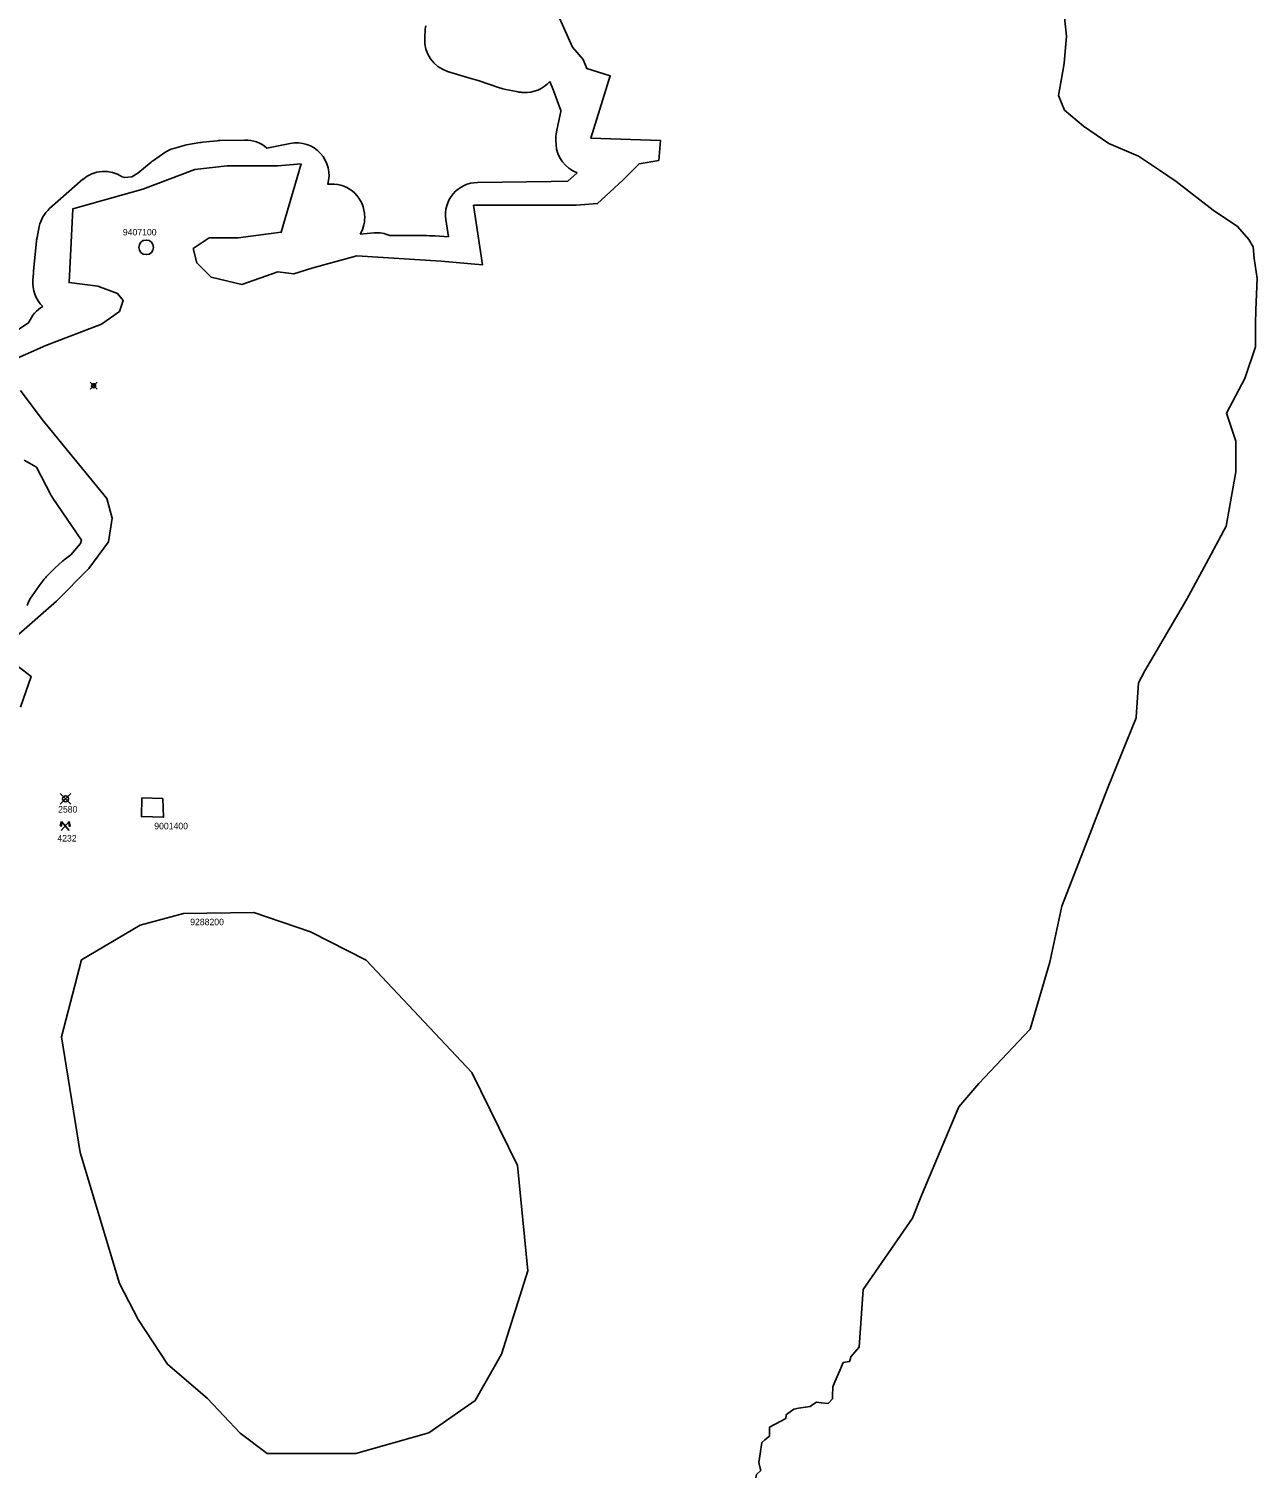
# Model space of a CAD drawing. Extents: x -546762 to -536351, y -1046851 to -1035695.
# Drawn here: x -542331 to -540434, y -1043037 to -1040804 of the extents above; entities that cross this region are included whole.
import ezdxf

# ---------------------------------------------------------------- set-up
doc = ezdxf.new("R2010")
doc.units = 0
for name, color, linetype in [('Vrstva 23', 7, 'Continuous'), ('Vrstva 24', 7, 'Continuous'), ('Vrstva 43', 7, 'Continuous'), ('Vrstva 49', 7, 'Continuous'), ('Vrstva 50', 7, 'Continuous'), ('Vrstva 53', 7, 'Continuous')]:
    doc.layers.add(name, color=color, linetype=linetype)

msp = doc.modelspace()

# ---------------------------------------------------------------- linework, layer by layer
at = {"layer": 'Vrstva 23'}
for points in [[(-541718.7, -1040804.2), (-541719.6, -1040818.5)], [(-541684.4, -1040869.7), (-541653.4, -1040879.2)], [(-541652.1, -1040879.6), (-541637.2, -1040883.7), (-541603.9, -1040895.3)], [(-541597, -1040897.2), (-541575.4, -1040901.4)], [(-541569.2, -1040902.2), (-541567.4, -1040902.3)], [(-541526.5, -1040885.3), (-541520.9, -1040899.1), (-541509.4, -1040930.2), (-541509.6, -1040931.9), (-541513.6, -1040950.9), (-541516.2, -1040963.1)], [(-542091.3, -1040984.3), (-542105.7, -1040988.2)], [(-542066.8, -1040979.7), (-542087.3, -1040983.4)], [(-542040.1, -1040976.8), (-542062.9, -1040979.1)], [(-541997.7, -1040975.7), (-542036.2, -1040976.6)], [(-541927.3, -1040981), (-541963.3, -1040988.3)], [(-541517.1, -1040976.5), (-541516.8, -1040982.4)], [(-542142.3, -1041009.9), (-542162.5, -1041026.7), (-542172.2, -1041032.5), (-542182.9, -1041033.6), (-542186.9, -1041032.4)], [(-542120.9, -1040995.1), (-542138.6, -1041007.2)], [(-542247.6, -1041036.4), (-542298.9, -1041081.5)], [(-541484.2, -1041026.3), (-541498.6, -1041039.1), (-541524.2, -1041039.6), (-541638.2, -1041041.2)], [(-541812.5, -1041090.9), (-541812.7, -1041088.9)], [(-541686.9, -1041098.6), (-541683, -1041125.1), (-541703.5, -1041123.9), (-541712.2, -1041123.4), (-541712.2, -1041123.4), (-541717.1, -1041123.1)], [(-542315, -1041109.4), (-542318.4, -1041126.4)], [(-541797.8, -1041119.1), (-541819.2, -1041121)], [(-541720.1, -1041123), (-541773.6, -1041123)], [(-542319.1, -1041131.5), (-542323.6, -1041178.4), (-542323.9, -1041181.9)], [(-542323.9, -1041181.9), (-542324.8, -1041191.7)], [(-542330.9, -1041257.1), (-542331.1, -1041257.4), (-542348.4, -1041269.3)], [(-542338.1, -1041469.8), (-542319, -1041480.8), (-542297.2, -1041523.3)], [(-542294.1, -1041528.6), (-542249.8, -1041593.7), (-542251.2, -1041598.6), (-542266.4, -1041615.9), (-542276.4, -1041623.8)], [(-542292.3, -1041638.1), (-542304, -1041650)], [(-542278.9, -1041625.9), (-542290.1, -1041636)], [(-542308.9, -1041655.7), (-542314.9, -1041664), (-542326, -1041679.3)]]:
    msp.add_lwpolyline(points, dxfattribs=at)
for centre, start, end in [((-541668.8, -1040807.6), 170.549, 176.1275), ((-541669.7, -1040821.9), 176.1275, 252.9674), ((-541638.7, -1040831.4), 252.9674, 254.5029), ((-541587.5, -1040848.1), 250.7987, 259.0889), ((-541565.9, -1040852.3), 259.0889, 266.2483), ((-541564.1, -1040852.4), 266.2483, 318.7681), ((-541467.2, -1040973.5), 168.1042, 183.4741), ((-542092.8, -1041036.5), 104.9586, 124.2627), ((-542078.4, -1041032.6), 100.3269, 104.9586), ((-542057.8, -1041028.9), 95.8202, 100.3269), ((-542035, -1041026.6), 91.3381, 95.8202), ((-541996.5, -1041025.7), 48.3603, 91.3381), ((-541917.4, -1041030.1), 343.6813, 101.3798), ((-541466.9, -1040979.4), 183.4741, 249.7552), ((-542110.4, -1041048.5), 124.2627, 129.5469), ((-542214.6, -1041074), 56.332, 131.2869), ((-541862.5, -1041093.6), 5.4, 97.9371), ((-541637.5, -1041091.2), 90.8025, 188.4933), ((-542265.9, -1041119.1), 131.2869, 168.7675), ((-541862.3, -1041095.6), 329.5491, 5.4), ((-542269.3, -1041136.2), 168.7675, 174.5913), ((-541793.5, -1041168.9), 66.5513, 95.0005), ((-541720.1, -1041173), 86.5922, 90.0098), ((-542275, -1041196.4), 174.5845, 226.4359), ((-542274.1, -1041186.6), 174.5362, 174.5845), ((-542284.6, -1041276), 119.8655, 157.8197), ((-542252.7, -1041500.5), 207.2129, 214.1842), ((-542256.7, -1041673.1), 132.0575, 135.4591), ((-542245.4, -1041663), 128.3522, 132.0575), ((-542268.4, -1041685.1), 135.4591, 143.9971), ((-542285.6, -1041708.7), 143.9771, 163.5215)]:
    msp.add_arc(centre, 50, start, end, dxfattribs=at)
at = {"layer": 'Vrstva 24'}
for points in [[(-541524.7, -1040757.2), (-541491.4, -1040832.2), (-541474.7, -1040851.6), (-541469.1, -1040865.5), (-541433, -1040876.6), (-541462.9, -1040973), (-541355.3, -1040976.6), (-541358.1, -1041007.1), (-541388.6, -1041012.7), (-541413.6, -1041037.7), (-541452.5, -1041073.8), (-541485.8, -1041076.5), (-541524.7, -1041076.5), (-541644.1, -1041076.5), (-541630.2, -1041168.2), (-541694.1, -1041162.6), (-541824.6, -1041154.3), (-541894, -1041173.7), (-541921.8, -1041182.1), (-541946.7, -1041179.3), (-542002.3, -1041198.7), (-542049.5, -1041187.6), (-542071.7, -1041165.4), (-542077.3, -1041143.2), (-542052.3, -1041126.5), (-542007.8, -1041126.5), (-541941.2, -1041118.2), (-541910.6, -1041012.7), (-541946.7, -1041015.5), (-542024.5, -1041015.5), (-542074.5, -1041021), (-542155, -1041051.6), (-542263.3, -1041082.1), (-542268.9, -1041195.9), (-542224.4, -1041201.5), (-542193.9, -1041212.6), (-542185.5, -1041223.7), (-542191.1, -1041240.4), (-542218.9, -1041259.8), (-542304.9, -1041293.1), (-542367.4, -1041320.7)], [(-541208.2, -1043041.3), (-541207.2, -1043036), (-541200.7, -1043029.6), (-541201.5, -1043025.9), (-541203.4, -1043017.2), (-541201.4, -1043003.8), (-541198.9, -1042986.3), (-541194.1, -1042982.3), (-541187.3, -1042976.7), (-541187.2, -1042969.9), (-541187.1, -1042962.8), (-541178.5, -1042958.3), (-541162, -1042949.7), (-541161.4, -1042943.7), (-541159, -1042941.9), (-541149.7, -1042934.8), (-541142.1, -1042933.7), (-541124.3, -1042930.9), (-541120.2, -1042928.1), (-541114.7, -1042924.5), (-541107.2, -1042925.2), (-541096.7, -1042926.2), (-541090, -1042919.3), (-541089.8, -1042915), (-541089.2, -1042900.7), (-541086, -1042893.1), (-541078.4, -1042875.2), (-541073.3, -1042863.2), (-541067.4, -1042862.1), (-541063.4, -1042861.4), (-541062.1, -1042856.6), (-541061.4, -1042854.1), (-541052.2, -1042843.7), (-541048.5, -1042839.5), (-541042.6, -1042750.2), (-540966.5, -1042640.3), (-540952.4, -1042605.2), (-540894.8, -1042468.2), (-540863.6, -1042432.3), (-540784.3, -1042348.4), (-540753.9, -1042245.2), (-540735.6, -1042158.4), (-540698.3, -1042063.5), (-540664.9, -1041976.7), (-540620.8, -1041867.7), (-540620.7, -1041866.5), (-540617.2, -1041813.7), (-540607.4, -1041795), (-540542.4, -1041684.7), (-540512.7, -1041629.5), (-540481.6, -1041572), (-540466.9, -1041488.1), (-540466.7, -1041440.7), (-540481.4, -1041397.5), (-540452.8, -1041343.7), (-540436.6, -1041295), (-540436.6, -1041255.9), (-540436.2, -1041241), (-540436.2, -1041237.7), (-540434.1, -1041189.6), (-540438.6, -1041158.6), (-540440.3, -1041140.5), (-540446.9, -1041129.5), (-540464.2, -1041109.2), (-540501.8, -1041084.2), (-540558.9, -1041039.9), (-540584.7, -1041022.3), (-540617.3, -1041000.7), (-540663.1, -1040981.3), (-540701.9, -1040954.1), (-540731.5, -1040929.6), (-540740.7, -1040906.9), (-540732.4, -1040860.8), (-540732, -1040857.1), (-540728.2, -1040815.2), (-540735.1, -1040752.1)], [(-542343.8, -1041362.6), (-542310.5, -1041407), (-542210.5, -1041529.2), (-542202.2, -1041559.7), (-542207.8, -1041595.8), (-542238.3, -1041637.4), (-542288.3, -1041687.4), (-542354.9, -1041745.7)], [(-542374.4, -1041768), (-542327.2, -1041804.1), (-542343.8, -1041851.3)]]:
    msp.add_lwpolyline(points, dxfattribs=at)
at = {"layer": 'Vrstva 43'}
for points in [[(-542156.6, -1041991.2), (-542124.2, -1041992.3), (-542123, -1042021.3), (-542157.2, -1042020.1)], [(-542249.8, -1042241.2), (-542158.9, -1042187.9), (-542092.3, -1042170), (-541983.6, -1042168.2), (-541896.2, -1042198.3), (-541809.9, -1042241.7), (-541646.8, -1042415.3), (-541576.2, -1042558.9), (-541560.5, -1042721.5), (-541601, -1042850), (-541641.6, -1042921.7), (-541713.3, -1042971.5), (-541826.2, -1043003.3), (-541962.7, -1043003.3), (-542004.4, -1042972.1), (-542055.3, -1042918.8), (-542116.7, -1042865.6), (-542162.1, -1042796.4), (-542191, -1042740.9), (-542251.8, -1042538.9), (-542280.4, -1042360.4)]]:
    msp.add_lwpolyline(points, close=True, dxfattribs=at)
msp.add_circle((-542149.8, -1041141.4), 11.3, dxfattribs=at)
at = {"layer": 'Vrstva 49'}
for p, q in [((-542236.5, -1041360.5), (-542225.5, -1041349.5)), ((-542236.5, -1041349.5), (-542225.5, -1041360.5))]:
    msp.add_line(p, q, dxfattribs=at)
msp.add_circle((-542231, -1041355), 3.08, dxfattribs=at)
at = {"layer": 'Vrstva 50'}
for p, q in [((-542282.5, -1042001.1), (-542266, -1041984.5)), ((-542282.5, -1041984.5), (-542266, -1042001.1))]:
    msp.add_line(p, q, dxfattribs=at)
msp.add_circle((-542274.3, -1041992.8), 4.61, dxfattribs=at)
at = {"layer": 'Vrstva 53'}
for p, q in [((-542280.5, -1042027.7), (-542280.5, -1042027.7)), ((-542268.9, -1042027.8), (-542268.9, -1042027.9))]:
    msp.add_line(p, q, dxfattribs=at)
for points in [[(-542280.5, -1042027.7), (-542282.5, -1042034.7), (-542280.5, -1042034.7), (-542280.5, -1042027.7)], [(-542280.9, -1042041.7), (-542268.9, -1042027.8)], [(-542268.6, -1042041.6), (-542280.5, -1042027.7), (-542280.5, -1042027.7)], [(-542268.9, -1042027.9), (-542267, -1042034.8), (-542268.9, -1042034.8), (-542268.9, -1042027.8)]]:
    msp.add_lwpolyline(points, dxfattribs=at)

# ---------------------------------------------------------------- texts
at = {"layer": 'Vrstva 43'}
for s, p in [('9407100', (-542185.8, -1041123)), ('9001400', (-542137.3, -1042039.8)), ('9288200', (-542081.8, -1042187.9))]:
    msp.add_text(s, height=10, dxfattribs=at).set_placement(p)
at = {"layer": 'Vrstva 50'}
msp.add_text('2580', height=10, dxfattribs=at).set_placement((-542285.8, -1042014))
at = {"layer": 'Vrstva 53'}
msp.add_text('4232', height=10, dxfattribs=at).set_placement((-542287, -1042058.7))

doc.saveas('drawing.dxf')
